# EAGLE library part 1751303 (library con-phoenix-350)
MKDS 1/ 8-3,5 Printklemme Nennstrom: 10 A Bemessungsspannung: 160 V Raster: 3,5 mm Polzahl: 8 Montageart: Löten Anschlussart: Schraubanschluss Anschlussrichtung vom Leiter zur Platine: 0° Source: http://eshop.phoenixcontact.com .. .pdf
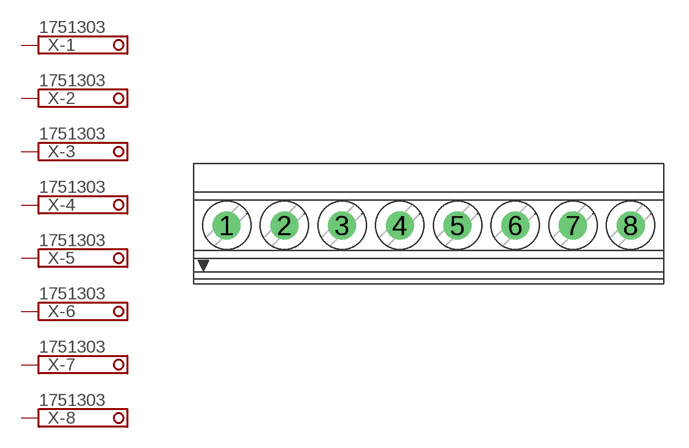
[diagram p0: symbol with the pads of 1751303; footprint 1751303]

Designator prefix X; gates -1=SCHRAUBKLEMME -2=SCHRAUBKLEMME -3=SCHRAUBKLEMME -4=SCHRAUBKLEMME -5=SCHRAUBKLEMME -6=SCHRAUBKLEMME -7=SCHRAUBKLEMME -8=SCHRAUBKLEMME

## 1751303 (OC_FARNELL: unknown; OC_NEWARK: unknown)  [1751303]
1  -1:K  pas
2  -2:K  pas
3  -3:K  pas
4  -4:K  pas
5  -5:K  pas
6  -6:K  pas
7  -7:K  pas
8  -8:K  pas

## Footprint 1751303 (pad centres in mm)
MKDS 1/ 8-3,5 Printklemme Nennstrom: 10 A Bemessungsspannung: 160 V Raster: 3,5 mm Polzahl: 8 Montageart: Löten Anschlussart: Schraubanschluss Anschlussrichtung vom Leiter zur Platine: 0° Source: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
drill 1.1 pad 1.7 round: 1 -12.25,-0.1; 2 -8.75,-0.1; 3 -5.25,-0.1; 4 -1.75,-0.1; 5 1.75,-0.1; 6 5.25,-0.1; 7 8.75,-0.1; 8 12.25,-0.1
